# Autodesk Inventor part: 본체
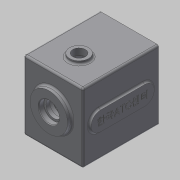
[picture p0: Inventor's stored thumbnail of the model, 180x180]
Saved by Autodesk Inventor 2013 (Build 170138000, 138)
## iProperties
Created: 2016-02
Part Number: 본체
Material: 일반
Document SubType Name: Modeling
Designer: mduedu
Density: 2.71 g/cm^3
Author: mduedu
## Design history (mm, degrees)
sketch "스케치1"
  geometry: L1 (-47, -47)-(47, -47); L2 (47, -47)-(47, 63); L3 (47, 63)-(-47, 63); L4 (-47, 63)-(-47, -47); 2 further points
  constraints: 8 end point, 2 parallel, 1 horizontal, 1 midpoint, 1 perpendicular, 1 vertical alignment
  dimensions: "d0" = 94 distance of L2.end L3.end; "d155" = 110 distance of L1.end L2.end; "d156" = 47 distance from line of L1 point (0, 0)
extrude "돌출1" new body sketch "스케치1" distance "d2" = 120; taper "d3" = 0 deg
sketch "스케치3"
  geometry: L1 (47, -47)-(-47, -47) reference; L2 (47, 63)-(47, -47) reference; L3 (-47, 63)-(47, 63) reference; L4 (-47, -47)-(-47, 63) reference; L5 (37, 53)-(37, -37); L6 (37, -37)-(-37, -37); L7 (-37, -37)-(-37, 53); L8 (-37, 53)-(37, 53); 1 further point
  constraints: 8 end point, 3 other
  dimensions: "d226" = 10 distance between parallel lines of L8 L3
extrude "돌출3" cut sketch "스케치3" distance "d11" = 110; taper "d12" = 0 deg
sketch "스케치4"
  geometry: C1 r 21 at (0, 11); 1 further point
  constraints: 1 centre point, 1 vertical alignment
  dimensions: "d13" = 21 radius of C1; "d227" = 11 distance of point (0, 0) C1.centre
extrude "돌출4" join sketch "스케치4" distance "d16" = 7; taper "d17" = 0 deg
sketch "스케치5"
  geometry: C1 r 15 at (0, -20); 1 further point
  constraints: 1 centre point, 1 vertical alignment
  dimensions: "d18" = 15 radius of C1; "d20" = 20 distance of point (0, 0) C1.centre
extrude "돌출5" join sketch "스케치5" distance "d21" = 7; taper "d22" = 0 deg
sketch "스케치6"
  geometry: C1 r 30 at (0, 11); A1 r 21 centre (0, 11) between (8.978, -7.984) and (-8.978, -7.984) reference; 1 further point
  constraints: 1 centre point, 1 coincident
  dimensions: "d228" = 60 diameter of C1
extrude "돌출6" join sketch "스케치6" distance "d25" = 7; taper "d26" = -3 deg
hole "구멍1" diameter "d29" = 35; stored, may be unused: countersink angle "d33" = 90 deg, drill point angle "d35" = 0 deg; dims "d27" = 10, "d28" = 10, "d30" = 6, "d31" = 4, "d32" = 2, "d34" = 10
hole "구멍2" diameter "d38" = 22; stored, may be unused: countersink angle "d42" = 90 deg, drill point angle "d44" = 0 deg; dims "d36" = 10, "d37" = 10, "d39" = 6, "d40" = 4, "d41" = 2, "d43" = 7
hole "구멍3" diameter "d47" = 19; stored, may be unused: countersink angle "d51" = 90 deg, drill point angle "d53" = 0 deg; dims "d45" = 10, "d46" = 10, "d48" = 6, "d49" = 4, "d50" = 2, "d52" = 1
hole "구멍4" diameter "d56" = 32; stored, may be unused: countersink angle "d60" = 90 deg, drill point angle "d62" = 0 deg; dims "d57" = 6, "d58" = 4, "d59" = 2, "d61" = 8, "d220" = 10, "d221" = 10
hole "구멍5" diameter "d65" = 25; stored, may be unused: countersink angle "d69" = 90 deg, drill point angle "d71" = 0 deg; dims "d63" = 10, "d64" = 10, "d66" = 6, "d67" = 4, "d68" = 2, "d70" = 8
fillet "모깎기2" dims "d73" = 0.3
fillet "모깎기3" dims "d74" = 2
chamfer "모따기1" distance "d75" = 1; stored, may be unused: second distance "d76" = 2, angle "d77" = 45 deg
fillet "모깎기4" dims "d78" = 3
fillet "모깎기23" dims "d240" = 1
fillet "모깎기20" dims "d229" = 3
sketch "스케치23"
  geometry: L1 (-37, 53)-(37, 53) reference; L2 (37, 53)-(37, -37) reference; L3 (37, -37)-(-37, -37) reference; L4 (-37, -37)-(-37, 53) reference; L5 (44, -47)-(-44, -47) reference; L6 (47, 60)-(47, -44) reference; L7 (-44, 63)-(44, 63) reference; L8 (-47, -44)-(-47, 60) reference; C1 r 10 at (-37, 53); C2 r 10 at (37, 53); C3 r 10 at (-37, -37); C4 r 10 at (37, -37); A1 r 3 centre (-44, -44) between (-47, -44) and (-44, -47) reference; A2 r 3 centre (44, -44) between (44, -47) and (47, -44) reference; A3 r 3 centre (44, 60) between (47, 60) and (44, 63) reference; A4 r 3 centre (-44, 60) between (-44, 63) and (-47, 60) reference; 1 further point
  constraints: 4 centre point, 4 coincident, 3 equal radius
  dimensions: "d230" = 20 diameter of C1
extrude "돌출22" join sketch "스케치23" stored distance "d235" = 10; taper "d236" = 0 deg
fillet "모깎기21" dims "d237" = 3
node "작업 평면1"
fillet "모깎기22" dims "d239" = 1
sketch "스케치12"
  geometry: A1 r 10 centre (-37, 53) between (-34.692, 43.27) and (-27.27, 50.692) reference; A2 r 10 centre (37, 53) between (27.27, 50.692) and (34.692, 43.27) reference; A3 r 10 centre (37, -37) between (34.692, -27.27) and (27.27, -34.692) reference; A4 r 10 centre (-37, -37) between (-27.27, -34.692) and (-34.692, -27.27) reference; 5 further points
  constraints: 4 coincident
hole "구멍6" sketch "스케치12" at (-37, 53), (37, 53), (37, -37), (-37, -37) diameter "d122" = 3.242; stored, may be unused: countersink angle "d126" = 90 deg, drill point angle "d128" = 120 deg; dims "d123" = 7, "d124" = 4, "d125" = 2, "d127" = 9
sketch "스케치20"
  geometry: L1 (44, 0)-(-44, 0) reference; L2 (44, -120)-(-44, -120) reference; L3 (0, 0)-(0, -120); L4 (-44, -120)-(-44, 0) reference; L5 (44, 0)-(44, -120) reference; C1 r 10 at (0, -79)
  constraints: 2 end point, 1 centre point, 1 midpoint, 1 point on line
  dimensions: "d189" = 20 diameter of C1; "d190" = 41 distance from line of C1.centre L2
extrude "돌출19" cut sketch "스케치20" stored distance "d191" = 10; taper "d192" = 0 deg
sketch "스케치18"
  geometry: C1 r 15 at (0, -79); C2 r 10 at (0, -79) reference; 1 further point
  constraints: 1 centre point, 1 concentric
  dimensions: "d174" = 30 diameter of C1
extrude "돌출17" join sketch "스케치18" distance "d175" = 5; taper "d176" = 0 deg
fillet "모깎기16" dims "d177" = 3
sketch "스케치19"
  geometry: C1 r 15 at (24.351, 79); C2 r 10 at (24.351, 79) reference; 1 further point
  constraints: 1 centre point, 1 concentric
  dimensions: "d178" = 30 diameter of C1
extrude "돌출18" cut sketch "스케치19" distance "d181" = 5; taper "d182" = 0 deg
chamfer "모따기5" distance "d183" = 1; stored, may be unused: second distance "d184" = 2, angle "d185" = 45 deg
fillet "모깎기24" dims "d242" = 3, "d243" = 3
sketch "스케치24"
  geometry: L1 (-95, 67)-(-25, 67); L2 (-25, 67)-(-25, 37); L3 (-25, 37)-(-95, 37); L4 (-95, 37)-(-95, 67); L5 (0, 0)-(0, 104) reference; L6 (-95, 52)-(-25, 52); L7 (-60, 67)-(-60, 37); A1 r 15 centre (-95, 52) between (-95, 37) and (-95, 67); A2 r 15 centre (-25, 52) between (-25, 67) and (-25, 37); A3 r 15 centre (-25, 52) between (-25, 37) and (-25, 67); A4 r 15 centre (-95, 52) between (-95, 67) and (-95, 37); 2 further points
  constraints: 12 end point, 8 point on circle, 5 midpoint, 4 centre point, 2 parallel, 2 perpendicular, 1 horizontal, 1 horizontal alignment
  dimensions: "d244" = 60 distance between parallel lines of L7 L5; "d245" = 100 dimension on A2 A1; "d246" = 30 distance between parallel lines of L3 L1
extrude "돌출23" join sketch "스케치24" distance "d247" = 3; taper "d248" = 0 deg
fillet "모깎기25" dims "d249" = 3
sketch "스케치25"
  geometry: L1 (-25, 67)-(-95, 67) reference; L2 (-95, 37)-(-25, 37) reference; A1 r 15 centre (-95, 52) between (-95, 67) and (-95, 37) reference; A2 r 15 centre (-25, 52) between (-25, 37) and (-25, 67) reference; 3 further points
  constraints: 1 horizontal alignment, 1 midpoint, 1 vertical alignment, 1 other
feature "엠보싱3" sketch "스케치25" dims "d250" = 0.5, "d251" = 0
sketch "스케치26"
  geometry: L1 (14.367, 127)-(73.633, 127) reference; L2 (0, 0)-(88, 0) reference; L3 (88, 120)-(0, 120) reference; 5 further points
  constraints: 3 vertical alignment, 2 midpoint
  dimensions: "d252" = 35 distance from line of point (44, 35) L2; "d253" = 35 distance from line of point (44, 85) L3; "d254" = 50 distance of point (44, 35) point (44, 85) (derived)
hole "구멍8" sketch "스케치26" at (44, 85), (44, 35) diameter "d255" = 6.647; stored, may be unused: countersink angle "d259" = 90 deg, drill point angle "d261" = 118 deg; dims "d256" = 6, "d257" = 4, "d258" = 2, "d260" = 8
node "솔리드1"
node "투영된 루프1"
node "투영된 루프4"
node "투영된 루프5"
node "투영된 루프6"
